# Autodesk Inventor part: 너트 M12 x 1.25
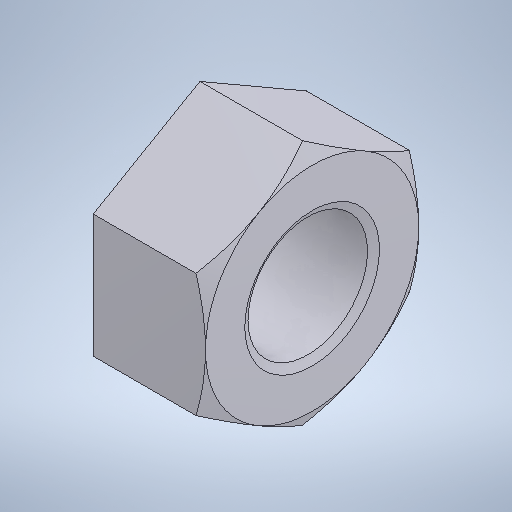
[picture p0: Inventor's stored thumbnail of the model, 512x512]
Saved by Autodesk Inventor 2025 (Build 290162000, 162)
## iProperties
Created: 2024-08
Part Number: 너트 M12 x 1.25
Material: 스테인리스강
Description: 6각 너트
Document SubType Name: Modeling
Designer: deana
Density: 8.08 g/cm^3
Appearance: 기본값
Author: jhkim
Sending System: Autodesk Inventor 2025
Preprocessor: ST-DEVELOPER v20
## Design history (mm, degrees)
feature "Solid1"
node "솔리드1"
